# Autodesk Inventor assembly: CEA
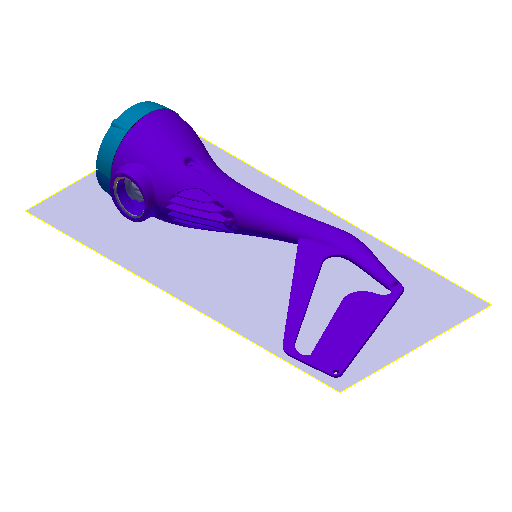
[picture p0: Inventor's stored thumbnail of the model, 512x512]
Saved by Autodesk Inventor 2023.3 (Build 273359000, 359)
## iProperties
Created: 2018-09
Part Number: CEA
Material: Générique
Document SubType Name: Assembly
Designer: SI
Author: SI
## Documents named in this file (9)
- C:\Travail\BTS TechCom\2-TechnoIndus\21-Meca\214-Systémes Industriels-SI\2141-Pièces Ecrites\21411-Cycle1\214112-TP02Eolienne\2141122-DossierTechniqueEolienne\21411223-Maquette numerique\214112231-CEA-Eolienne\CEA.iam
- C:\Travail\BTS TechCom\2-TechnoIndus\21-Meca\214-Systémes Industriels-SI\2141-Pièces Ecrites\21411-Cycle1\214112-TP02Eolienne\2141122-DossierTechniqueEolienne\21411223-Maquette numerique\214112231-CEA-Eolienne\01-Nacelle.ipt
- C:\Travail\BTS TechCom\2-TechnoIndus\21-Meca\214-Systémes Industriels-SI\2141-Pièces Ecrites\21411-Cycle1\214112-TP02Eolienne\2141122-DossierTechniqueEolienne\21411223-Maquette numerique\214112231-CEA-Eolienne\13-Stator.ipt
- C:\Travail\BTS TechCom\2-TechnoIndus\21-Meca\214-Systémes Industriels-SI\2141-Pièces Ecrites\21411-Cycle1\214112-TP02Eolienne\2141122-DossierTechniqueEolienne\21411223-Maquette numerique\214112231-CEA-Eolienne\14-Joint torique.ipt
- C:\Travail\BTS TechCom\2-TechnoIndus\21-Meca\214-Systémes Industriels-SI\2141-Pièces Ecrites\21411-Cycle1\214112-TP02Eolienne\2141122-DossierTechniqueEolienne\21411223-Maquette numerique\214112231-CEA-Eolienne\18-Circuit.ipt
- C:\Travail\BTS TechCom\2-TechnoIndus\21-Meca\214-Systémes Industriels-SI\2141-Pièces Ecrites\21411-Cycle1\214112-TP02Eolienne\2141122-DossierTechniqueEolienne\21411223-Maquette numerique\214112231-CEA-Eolienne\11-Face.ipt
- C:\Travail\BTS TechCom\2-TechnoIndus\21-Meca\214-Systémes Industriels-SI\2141-Pièces Ecrites\21411-Cycle1\214112-TP02Eolienne\2141122-DossierTechniqueEolienne\21411223-Maquette numerique\214112231-CEA-Eolienne\24-NF E 25-125 - M5 x 35.ipt
- C:\Travail\BTS TechCom\2-TechnoIndus\21-Meca\214-Systémes Industriels-SI\2141-Pièces Ecrites\21411-Cycle1\214112-TP02Eolienne\2141122-DossierTechniqueEolienne\21411223-Maquette numerique\214112231-CEA-Eolienne\12-NF E 22-165 - 42x1,75.ipt
- C:\Travail\BTS TechCom\2-TechnoIndus\21-Meca\214-Systémes Industriels-SI\2141-Pièces Ecrites\21411-Cycle1\214112-TP02Eolienne\2141122-DossierTechniqueEolienne\21411223-Maquette numerique\214112231-CEA-Eolienne\03-NF E 22-165 - 62x2.ipt
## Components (12 placed, 8 different names)
1. 01-Nacelle:1 — Placage:1, Placage:2, Placage:3, Angle:2, Logement:5, Logement:11, Logement:17, Logement:19, Placage:6
2. 13-Stator:1 — Angle:2, Logement:5, Angle:3
3. 14-Joint torique:1 — Placage:1, Placage:2
4. 18-Circuit:1 — Logement:9, Logement:10, Logement:11
5. NF E 25-125 M5 x 35:1 — Logement:15
6. NF E 25-125 M5 x 35:3 — Logement:13
7. NF E 25-125 M5 x 35:2 — Logement:18
8. NF E 25-125 M5 x 35:4 — Logement:10
9. NF E 25-125 M5 x 35:5 — Logement:9
10. 11-Face:1 — Angle:3, Logement:13, Logement:15, Logement:17, Logement:18, Placage:4, Placage:7
11. NF E 22-165 42x1,75:1 — Placage:4, Placage:6, Placage:7
12. NF E 22-165 62x2:1 — Logement:19
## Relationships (17: Insert 9, Mate 6, Angle 2)
- Placage:1 [Mate]: 01-Nacelle:1 ↔ 14-Joint torique:1
- Placage:2 [Mate]: 01-Nacelle:1 ↔ 14-Joint torique:1
- Placage:3 [Mate]: 01-Nacelle:1
- Angle:2: 01-Nacelle:1 ↔ 13-Stator:1
- Logement:5 [Insert]: 01-Nacelle:1 ↔ 13-Stator:1
- Logement:9 [Insert]: 18-Circuit:1 ↔ NF E 25-125 M5 x 35:5
- Logement:10 [Insert]: 18-Circuit:1 ↔ NF E 25-125 M5 x 35:4
- Logement:11 [Insert]: 01-Nacelle:1 ↔ 18-Circuit:1
- Angle:3: 13-Stator:1 ↔ 11-Face:1
- Logement:13 [Insert]: NF E 25-125 M5 x 35:3 ↔ 11-Face:1
- Logement:15 [Insert]: NF E 25-125 M5 x 35:1 ↔ 11-Face:1
- Logement:17 [Insert]: 01-Nacelle:1 ↔ 11-Face:1
- Logement:18 [Insert]: NF E 25-125 M5 x 35:2 ↔ 11-Face:1
- Logement:19 [Insert]: 01-Nacelle:1 ↔ NF E 22-165 62x2:1
- Placage:4 [Mate]: 11-Face:1 ↔ NF E 22-165 42x1,75:1
- Placage:6 [Mate]: 01-Nacelle:1 ↔ NF E 22-165 42x1,75:1
- Placage:7 [Mate]: 11-Face:1 ↔ NF E 22-165 42x1,75:1
